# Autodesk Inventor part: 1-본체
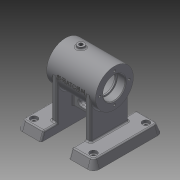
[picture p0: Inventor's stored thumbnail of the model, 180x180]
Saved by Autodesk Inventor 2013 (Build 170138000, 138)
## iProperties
Created: 2016-07
Part Number: 1-본체
Material: 일반
Document SubType Name: Modeling
Designer: WINDOWS7
Density: 1 g/cm^3
Author: WINDOWS7
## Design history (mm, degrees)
sketch "스케치1"
  geometry: C1 r 27 at (0, 0); 1 further point
  constraints: 1 centre point, 1 coincident
  dimensions: "d0" = 54 diameter of C1
extrude "돌출1" new body sketch "스케치1" stored distance "d1" = 70; taper "d2" = 0 deg
node "작업 평면1"
sketch "스케치3"
  geometry: L1 (-50, -70)-(50, -70); L2 (50, -70)-(45.632, -58); L3 (45.632, -58)-(-45.632, -58); L4 (-45.632, -58)-(-50, -70); 2 further points
  constraints: 8 end point, 1 horizontal, 1 midpoint, 1 parallel, 1 vertical alignment
  dimensions: "d7" = 70 deg angle of L1 L4; "d8" = 70 deg angle of L1 L2; "d9" = 12 distance between parallel lines of L1 L3; "d11" = 70 distance from line of L1 point (0, 0); "d12" = 100 distance of L1.start L1.end
extrude "돌출2" join sketch "스케치3" distance "d13" = 35; taper "d14" = 0 deg
sketch "스케치5"
  geometry: L1 (-55, -58)-(-55, -70) reference; L2 (-55, -58)-(-20, -58) reference; L3 (-55, -70)-(-20, -70) reference; L4 (-55, -58)-(-55, -70); L5 (-55, -70)-(-50.632, -58); L6 (-50.632, -58)-(-55, -58); 1 further point
  constraints: 6 end point, 1 collinear, 1 perpendicular, 1 point on line
  dimensions: "d16" = 70 deg angle of L5 L6
extrude "돌출3" cut sketch "스케치5" stored distance "d17" = 35; taper "d18" = 0 deg
sketch "스케치6"
  geometry: L1 (0, 27)-(-64.229, 27); L2 (-64.229, 27)-(-64.229, -27); L3 (-64.229, -27)-(0, -27); L4 (0, -27)-(0, 27); C1 r 27 at (0, 0) reference; 2 further points
  constraints: 8 end point, 2 coincident, 2 parallel, 1 horizontal, 1 midpoint, 1 perpendicular
  dimensions: "d19" = 54 distance of L1.end L2.end
extrude "돌출4" join sketch "스케치6" distance "d21" = 8; taper "d22" = 0 deg
sketch "스케치7"
  geometry: 5 further points
  constraints: 2 horizontal alignment, 2 vertical alignment
  dimensions: "d23" = 85 distance of point (22.5, 83.132) point (-62.5, 83.132); "d25" = 75 distance of point (-62.5, 8.132) point (-62.5, 83.132); "d26" = 37.5 vertical distance of point (-20, 45.632) point (-62.5, 8.132); "d27" = 42.5 horizontal distance of point (-20, 45.632) point (22.5, 83.132)
hole "구멍1" sketch "스케치7" at (22.5, 83.132), (-62.5, 83.132), (-62.5, 8.132), (22.5, 8.132) diameter "d28" = 6; stored, may be unused: countersink angle "d32" = 90 deg, drill point angle "d34" = 118 deg; dims "d29" = 6, "d30" = 10, "d31" = 4, "d33" = 8
node "작업 평면2"
node "작업 평면3"
sketch "스케치8"
  geometry: L1 (-55, 77)-(-55, 23) reference; C1 r 5 at (-33, 50); 1 further point
  constraints: 1 centre point, 1 horizontal alignment
  dimensions: "d36" = 22 distance from line of L1 C1.centre; "d37" = 10 diameter of C1
extrude "돌출5" join sketch "스케치8" distance "d38" = 8; taper "d39" = 0 deg
sketch "스케치9"
  geometry: L1 (-20, -48)-(20, -48); L2 (-20, -58)-(-20, 0) reference; L3 (20, -58)-(20, 0) reference; L4 (35, -27)-(-35, -27) reference; L5 (-20, -20.108)-(20, -20.108); L6 (-20, -48)-(-20, -20.108); L7 (20, -48)-(20, -20.108); L8 (-8, -34.5)-(8, -34.5); L9 (8, -41.5)-(-8, -41.5); L10 (55, -70)-(20, -70) reference; A1 r 3.5 centre (-8, -38) between (-8, -34.5) and (-8, -41.5); A2 r 3.5 centre (8, -38) between (8, -41.5) and (8, -34.5); 3 further points
  constraints: 12 end point, 4 point on circle, 3 parallel, 3 tangent, 2 centre point, 2 collinear, 2 midpoint, 2 point on line, 1 vertical alignment
  dimensions: "d41" = 21 distance between parallel lines of L1 L4; "d42" = 7 diameter of A1; "d43" = 7 diameter of A2; "d44" = 32 distance from line of A2.centre L10; "d45" = 23 dimension on A2 A1
extrude "돌출6" join sketch "스케치9" stored distance "d46" = 8; taper "d47" = 0 deg
sketch "스케치10"
  geometry: L1 (35, 0)-(-35, 0); L2 (-35, 0)-(-35, 16); L3 (-35, 16)-(-23, 16); L4 (-23, 16)-(-23, 14); L5 (-23, 14)-(-21, 14); L6 (-21, 14)-(-21, 22); L7 (-21, 22)-(21, 22); L8 (21, 22)-(21, 14); L9 (21, 14)-(23, 14); L10 (23, 14)-(23, 16); L11 (23, 16)-(35, 16); L12 (35, 16)-(35, 0); L13 (35, -27)-(35, 27) reference; L14 (-35, 27)-(-35, -27) reference; 2 further points
  constraints: 24 end point, 10 parallel, 2 collinear, 1 coincident, 1 horizontal, 1 midpoint, 1 perpendicular
  dimensions: "d48" = 32 diameter of L3 L1; "d50" = 28 diameter of L5 L1; "d51" = 12 distance of L2.end L3.end; "d52" = 42 distance of L6.end L7.end; "d53" = 2 distance of L4.end L5.end; "d54" = 12 distance of L10.end L11.end; "d55" = 2 distance of L8.end L9.end (derived); "d56" = 32 diameter of L11 L1; "d57" = 28 diameter of L9 L1; "d58" = 44 diameter of L7 L1
revolve "회전1" sketch "스케치10" stored, may be unused: angle "d59" = 90 deg
hole "구멍2" diameter "d62" = 5.188; stored, may be unused: countersink angle "d66" = 90 deg, drill point angle "d68" = 118 deg; dims "d63" = 6, "d64" = 10, "d65" = 4, "d67" = 20, "d69" = 10, "d70" = 10
sketch "스케치11"
  geometry: C1 r 16 at (0, 0) reference; 1 further point
  constraints: 1 horizontal alignment
  dimensions: "d71" = 21 distance of C1.centre point (-21, 0)
hole "구멍3" sketch "스케치11" at (-21, 0) diameter "d72" = 3.242; stored, may be unused: countersink angle "d76" = 90 deg, drill point angle "d78" = 118 deg; dims "d73" = 8, "d74" = 10, "d75" = 4, "d77" = 10
node "작업 평면6"
  node "작업 평면5"
sketch "스케치12"
  geometry: C1 r 6 at (0, 0); 1 further point
  constraints: 1 centre point, 1 coincident
  dimensions: "d84" = 12 diameter of C1
extrude "돌출7" join sketch "스케치12" distance "d85" = 5; taper "d86" = 0 deg
hole "구멍4" diameter "d89" = 5.188; stored, may be unused: countersink angle "d93" = 90 deg, drill point angle "d95" = 118 deg; dims "d87" = 10, "d88" = 10, "d90" = 8, "d91" = 10, "d92" = 4, "d94" = 15
fillet "모깎기1" dims "d96" = 0.3
fillet "모깎기2" dims "d97" = 10, "d98" = 5
fillet "모깎기3" dims "d99" = 5, "d100" = 10
fillet "모깎기4" dims "d101" = 3
chamfer "모따기1" distance "d102" = 1; stored, may be unused: second distance "d103" = 2, angle "d104" = 45 deg
fillet "모깎기5" dims "d105" = 2
fillet "모깎기6" dims "d106" = 2
fillet "모깎기7" dims "d107" = 2
fillet "모깎기8" dims "d108" = 2
fillet "모깎기9" dims "d109" = 2
fillet "모깎기10" dims "d110" = 2
fillet "모깎기11" dims "d111" = 2
fillet "모깎기12" dims "d112" = 2
fillet "모깎기13" dims "d113" = 2
fillet "모깎기14" dims "d114" = 2
node "작업 평면7"
sketch "스케치13"
  geometry: L1 (-20.739, 3.002)-(20.739, 3.002); L2 (20.739, 3.002)-(20.739, -3.002); L3 (20.739, -3.002)-(-20.739, -3.002); L4 (-20.739, -3.002)-(-20.739, 3.002); L5 (-20.739, 0)-(20.739, 0); L6 (0, 3.002)-(0, -3.002); L7 (-35, 27)-(35, 27) reference; 2 further points
  constraints: 5 midpoint, 4 end point, 1 coincident, 2 other
  dimensions: "d115" = 27 distance from line of point (0, 0) L7
feature "엠보싱1" sketch "스케치13" dims "d16" = 70 deg, "d116" = 0.5, "d117" = 0
node "솔리드1"
mirror "대칭1"
mirror "대칭2"
pattern_circular "원형 패턴1" dims angle "d80" = 360 deg
mirror "대칭3"
mirror "대칭4"
node "작업 평면4"
other parameters: "d3" = 55, "d82" = 58 deg, "d83" = 3
